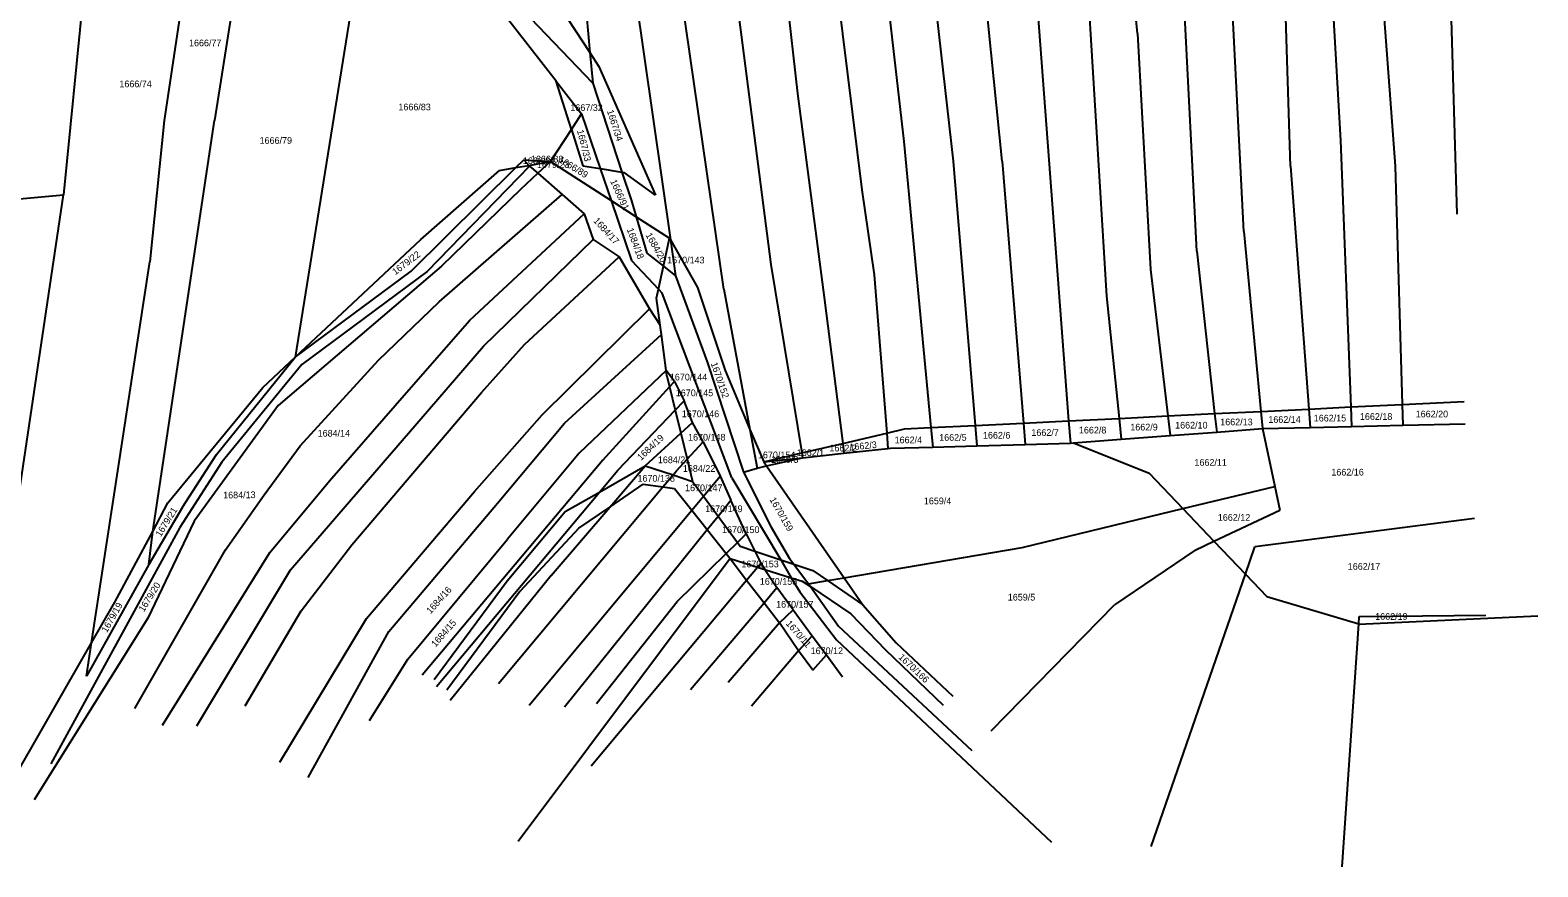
# Model space of a CAD drawing. Extents: x -563148 to -561712, y -1182311 to -1179502.
# Drawn here: x -562099.2 to -561761.9, y -1182279.2 to -1182092.2 of the extents above; entities that cross this region are included whole.
import ezdxf

# ---------------------------------------------------------------- set-up
doc = ezdxf.new("R2010")
doc.units = 0
for name, color, linetype in [('Vrstva 55', 7, 'Continuous'), ('Vrstva 56', 7, 'Continuous'), ('Vrstva 57', 7, 'Continuous')]:
    doc.layers.add(name, color=color, linetype=linetype)

msp = doc.modelspace()

# ---------------------------------------------------------------- linework, layer by layer
at = {"layer": 'Vrstva 55'}
for p, q in [((-561881.77, -1182121.42), (-561894.13, -1181998.39)), ((-561851.53, -1182092.93), (-561858.17, -1182019.92)), ((-561801.14, -1182025.11), (-561793.84, -1182122.58)), ((-561838.25, -1182141.59), (-561843.97, -1182028.63)), ((-561811.3, -1182027.71), (-561806.09, -1182116.85)), ((-561902.61, -1182034.14), (-561892.76, -1182121.42)), ((-562057.84, -1182035.8), (-562069.21, -1182112.37)), ((-561935.36, -1182036.2), (-561927.57, -1182106.3)), ((-561924.37, -1182037.34), (-561913.14, -1182127.84)), ((-561912.92, -1182038.03), (-561903.75, -1182117.07)), ((-562047.11, -1182043.71), (-562057.98, -1182112.37)), ((-562083.82, -1182048.76), (-562091.77, -1182128.98)), ((-562023.2, -1182061.34), (-562039.93, -1182165.3)), ((-561827.71, -1182137.18), (-561831.62, -1182061.07)), ((-561976.59, -1182067.81), (-561973.98, -1182097.18)), ((-561964.91, -1182076.75), (-561955.99, -1182139.02)), ((-561983.82, -1182082.17), (-561973.98, -1182097.18)), ((-561944.07, -1182150.06), (-561954.14, -1182080.19)), ((-561941.77, -1182080.64), (-561933.53, -1182144.56)), ((-561874.18, -1182082.99), (-561866.9, -1182179.5)), ((-561817.29, -1182122.58), (-561818.55, -1182080.87)), ((-561781.6, -1182079.84), (-561780.03, -1182133.27)), ((-561862.53, -1182084.31), (-561858.4, -1182151.67)), ((-561981.56, -1182103.54), (-561993.68, -1182088.01)), ((-561973.38, -1182104.01), (-561988.96, -1182087.75)), ((-561851.53, -1182092.93), (-561848.56, -1182145.71)), ((-561973.98, -1182097.18), (-561973.38, -1182104.01)), ((-561973.98, -1182097.18), (-561971.97, -1182100.26)), ((-561971.97, -1182100.26), (-561959.32, -1182129.02)), ((-561978.15, -1182114.35), (-561981.56, -1182103.54)), ((-561981.56, -1182103.54), (-561975.9, -1182110.89)), ((-561973.38, -1182104.01), (-561966.82, -1182123.89)), ((-561927.57, -1182106.3), (-561921.62, -1182151.9)), ((-562069.21, -1182112.37), (-562072.41, -1182143.99)), ((-562071.8, -1182204.21), (-562057.98, -1182112.37)), ((-561978.15, -1182114.35), (-561975.9, -1182110.89)), ((-561975.9, -1182110.89), (-561971.72, -1182123.11)), ((-561982.85, -1182121.56), (-561978.15, -1182114.35)), ((-561978.15, -1182114.35), (-561975.59, -1182122.49)), ((-561903.75, -1182117.07), (-561897.71, -1182181.01)), ((-561806.09, -1182116.85), (-561803.81, -1182176.41)), ((-562014.01, -1182146.05), (-561990.55, -1182122.9)), ((-561987.5, -1182122.54), (-562010.44, -1182146.1)), ((-561994.24, -1182123.55), (-561990.55, -1182122.9)), ((-561990.55, -1182122.9), (-561988.77, -1182121.15)), ((-561990.55, -1182122.9), (-561987.63, -1182122.4)), ((-561988.77, -1182121.15), (-561987.63, -1182122.4)), ((-561988.77, -1182121.15), (-561982.85, -1182121.56)), ((-561987.63, -1182122.4), (-561982.85, -1182121.56)), ((-561987.63, -1182122.4), (-561987.5, -1182122.54)), ((-561987.5, -1182122.54), (-561985.64, -1182124.17)), ((-561985.64, -1182124.17), (-561982.85, -1182121.56)), ((-561982.85, -1182121.56), (-561969.26, -1182130.27)), ((-561975.59, -1182122.49), (-561971.72, -1182123.11)), ((-561971.72, -1182123.11), (-561969.26, -1182130.27)), ((-561971.72, -1182123.11), (-561966.82, -1182123.89)), ((-561892.76, -1182121.42), (-561887.82, -1182180.52)), ((-561881.77, -1182121.42), (-561876.99, -1182179.99)), ((-561817.29, -1182122.58), (-561813.15, -1182176.86)), ((-561793.84, -1182122.58), (-561792.32, -1182175.84)), ((-562011.84, -1182139), (-561994.24, -1182123.55)), ((-561989.44, -1182127.73), (-561985.64, -1182124.17)), ((-561985.64, -1182124.17), (-561980.21, -1182128.92)), ((-561966.82, -1182123.89), (-561966.3, -1182123.97)), ((-561966.82, -1182123.89), (-561964.68, -1182130.36)), ((-561959.32, -1182129.02), (-561966.3, -1182123.97)), ((-562113.98, -1182278.04), (-562091.77, -1182128.98)), ((-562102.41, -1182129.95), (-562091.77, -1182128.98)), ((-562007.69, -1182152.89), (-561980.21, -1182128.92)), ((-561989.44, -1182127.73), (-562007.2, -1182144.91)), ((-561980.21, -1182128.92), (-561975.3, -1182133.22)), ((-561913.14, -1182127.84), (-561910.4, -1182146.85)), ((-562000.83, -1182156.97), (-561975.3, -1182133.22)), ((-561975.3, -1182133.22), (-561973.24, -1182138.95)), ((-561969.26, -1182130.27), (-561964.68, -1182143.65)), ((-561969.26, -1182130.27), (-561963.65, -1182133.87)), ((-561964.68, -1182130.36), (-561963.65, -1182133.87)), ((-561963.65, -1182133.87), (-561961.24, -1182142.04)), ((-561963.65, -1182133.87), (-561956.2, -1182138.64)), ((-562039.93, -1182165.3), (-562011.84, -1182139)), ((-561997.82, -1182162.81), (-561973.24, -1182138.95)), ((-561973.24, -1182138.95), (-561967.43, -1182142.83)), ((-561957.54, -1182144.94), (-561956.2, -1182138.64)), ((-561956.2, -1182138.64), (-561955.99, -1182139.02)), ((-561955.99, -1182139.02), (-561954.83, -1182147.08)), ((-561955.99, -1182139.02), (-561949.91, -1182149.71)), ((-561827.71, -1182137.18), (-561823.9, -1182177.39)), ((-561988.64, -1182162.47), (-561967.43, -1182142.83)), ((-561967.43, -1182142.83), (-561960.64, -1182154.47)), ((-561964.68, -1182143.65), (-561958.64, -1182150.09)), ((-561961.24, -1182142.04), (-561957.54, -1182144.94)), ((-561838.25, -1182141.59), (-561834.24, -1182177.9)), ((-562085.48, -1182229.17), (-562072.41, -1182143.99)), ((-562007.2, -1182144.91), (-562043.72, -1182176.06)), ((-562039.93, -1182165.3), (-562014.01, -1182146.05)), ((-562010.44, -1182146.1), (-562038.41, -1182166.89)), ((-561958.64, -1182150.09), (-561957.54, -1182144.94)), ((-561957.54, -1182144.94), (-561954.83, -1182147.08)), ((-561933.53, -1182144.56), (-561926.59, -1182186.68)), ((-561910.4, -1182146.85), (-561907.6, -1182182.23)), ((-561848.56, -1182145.71), (-561844.71, -1182178.41)), ((-561959.07, -1182152.09), (-561958.64, -1182150.09)), ((-561958.64, -1182150.09), (-561957.81, -1182150.98)), ((-561954.83, -1182147.08), (-561947.73, -1182166.33)), ((-561949.91, -1182149.71), (-561943.77, -1182168.27)), ((-561944.07, -1182150.06), (-561938.19, -1182181.42)), ((-562021.28, -1182165.97), (-562007.69, -1182152.89)), ((-561958.28, -1182158.1), (-561959.07, -1182152.09)), ((-561942.23, -1182192.24), (-561957.81, -1182150.98)), ((-561921.62, -1182151.9), (-561917.45, -1182184.54)), ((-561858.4, -1182151.67), (-561855.62, -1182178.95)), ((-562015.06, -1182173.19), (-562000.83, -1182156.97)), ((-561984.69, -1182178.17), (-561960.64, -1182154.47)), ((-561960.64, -1182154.47), (-561958.28, -1182158.1)), ((-561979.71, -1182180.06), (-561958, -1182160.23)), ((-561958, -1182160.23), (-561958.28, -1182158.1)), ((-561956.94, -1182168.22), (-561958, -1182160.23)), ((-562009.91, -1182176.8), (-561997.82, -1182162.81)), ((-561998.24, -1182173.19), (-561988.64, -1182162.47)), ((-562057.52, -1182187.06), (-562039.93, -1182165.3)), ((-562038.41, -1182166.89), (-562056.32, -1182188.73)), ((-562047.13, -1182172.04), (-562039.93, -1182165.3)), ((-562038.8, -1182185.06), (-562021.28, -1182165.97)), ((-561947.73, -1182166.33), (-561939.64, -1182190.99)), ((-561956.94, -1182168.22), (-561976.37, -1182186.76)), ((-561955.08, -1182170.68), (-561956.94, -1182168.22)), ((-561956.78, -1182169.45), (-561956.94, -1182168.22)), ((-561956.78, -1182169.45), (-561956.19, -1182171.9)), ((-561956.19, -1182171.9), (-561955.08, -1182170.68)), ((-561955.08, -1182170.68), (-561952.93, -1182175.06)), ((-561943.77, -1182168.27), (-561938.19, -1182181.42)), ((-562068.39, -1182197.84), (-562047.13, -1182172.04)), ((-562032.23, -1182192.94), (-562015.06, -1182173.19)), ((-562027.25, -1182207.19), (-561998.24, -1182173.19)), ((-561971.1, -1182188.27), (-561956.19, -1182171.9)), ((-561956.19, -1182171.9), (-561954.92, -1182177.14)), ((-562043.72, -1182176.06), (-562062.54, -1182201.9)), ((-562040.98, -1182212.85), (-562009.91, -1182176.8)), ((-561967.76, -1182190.56), (-561954.92, -1182177.14)), ((-561954.92, -1182177.14), (-561952.93, -1182175.06)), ((-561954.92, -1182177.14), (-561953.67, -1182182.29)), ((-561951.05, -1182179.89), (-561952.93, -1182175.06)), ((-561834.24, -1182177.9), (-561823.9, -1182177.39)), ((-561823.9, -1182177.39), (-561813.15, -1182176.86)), ((-561823.9, -1182177.39), (-561823.54, -1182181.23)), ((-561813.15, -1182176.86), (-561803.81, -1182176.41)), ((-561813.15, -1182176.86), (-561812.84, -1182180.98)), ((-561803.81, -1182176.41), (-561792.32, -1182175.84)), ((-561803.81, -1182176.41), (-561803.65, -1182180.77)), ((-561792.32, -1182175.84), (-561778.4, -1182175.16)), ((-561792.32, -1182175.84), (-561792.18, -1182180.5)), ((-561999.79, -1182195.34), (-561984.69, -1182178.17)), ((-561994.64, -1182197.92), (-561979.71, -1182180.06)), ((-561953.67, -1182182.29), (-561951.05, -1182179.89)), ((-561948.65, -1182184.18), (-561951.05, -1182179.89)), ((-561897.71, -1182181.01), (-561887.82, -1182180.52)), ((-561887.82, -1182180.52), (-561876.99, -1182179.99)), ((-561887.82, -1182180.52), (-561887.44, -1182185.09)), ((-561876.99, -1182179.99), (-561866.9, -1182179.5)), ((-561876.99, -1182179.99), (-561876.6, -1182184.77)), ((-561866.9, -1182179.5), (-561855.62, -1182178.95)), ((-561866.9, -1182179.5), (-561866.51, -1182184.48)), ((-561855.62, -1182178.95), (-561844.71, -1182178.41)), ((-561855.62, -1182178.95), (-561855.14, -1182183.64)), ((-561844.71, -1182178.41), (-561834.24, -1182177.9)), ((-561844.71, -1182178.41), (-561844.19, -1182182.81)), ((-561834.24, -1182177.9), (-561833.78, -1182182.01)), ((-561812.84, -1182180.98), (-561803.65, -1182180.77)), ((-561803.65, -1182180.77), (-561792.18, -1182180.5)), ((-561792.18, -1182180.5), (-561778.21, -1182180.18)), ((-561961.61, -1182189.57), (-561953.67, -1182182.29)), ((-561953.67, -1182182.29), (-561952.26, -1182188.11)), ((-561938.19, -1182181.42), (-561936.57, -1182190.05)), ((-561938.19, -1182181.42), (-561935.11, -1182188.67)), ((-561917.45, -1182184.54), (-561907.6, -1182182.23)), ((-561907.6, -1182182.23), (-561903.62, -1182181.3)), ((-561907.6, -1182182.23), (-561907.32, -1182185.71)), ((-561903.62, -1182181.3), (-561897.71, -1182181.01)), ((-561897.71, -1182181.01), (-561897.3, -1182185.37)), ((-561865.82, -1182184.46), (-561855.14, -1182183.64)), ((-561855.14, -1182183.64), (-561844.19, -1182182.81)), ((-561844.19, -1182182.81), (-561833.78, -1182182.01)), ((-561833.78, -1182182.01), (-561823.54, -1182181.23)), ((-561823.54, -1182181.23), (-561812.84, -1182180.98)), ((-561823.54, -1182181.23), (-561820.76, -1182194.18)), ((-562065.14, -1182198.78), (-562057.52, -1182187.06)), ((-562046.9, -1182196.04), (-562038.8, -1182185.06)), ((-561976.37, -1182186.76), (-561992.41, -1182205.99)), ((-561952.26, -1182188.11), (-561948.65, -1182184.18)), ((-561948.65, -1182184.18), (-561944.87, -1182191.91)), ((-561935.11, -1182188.67), (-561926.59, -1182186.68)), ((-561926.59, -1182186.68), (-561917.45, -1182184.54)), ((-561926.59, -1182186.68), (-561926.41, -1182187.74)), ((-561926.41, -1182187.74), (-561917.17, -1182186.76)), ((-561917.45, -1182184.54), (-561917.17, -1182186.76)), ((-561917.17, -1182186.76), (-561907.32, -1182185.71)), ((-561907.32, -1182185.71), (-561906.79, -1182185.65)), ((-561906.79, -1182185.65), (-561897.3, -1182185.37)), ((-561897.3, -1182185.37), (-561887.44, -1182185.09)), ((-561887.44, -1182185.09), (-561876.6, -1182184.77)), ((-561876.6, -1182184.77), (-561866.51, -1182184.48)), ((-561866.51, -1182184.48), (-561865.82, -1182184.46)), ((-561865.82, -1182184.46), (-561848.91, -1182191.2)), ((-562056.32, -1182188.73), (-562065.73, -1182203.37)), ((-561971.1, -1182188.27), (-562011.55, -1182236.39)), ((-561971.84, -1182195.42), (-561961.61, -1182189.57)), ((-561971.84, -1182195.42), (-561967.76, -1182190.56)), ((-561969.51, -1182198.78), (-561961.61, -1182189.57)), ((-561961.61, -1182189.57), (-561955.4, -1182191.61)), ((-561955.4, -1182191.61), (-561954.65, -1182190.71)), ((-561954.65, -1182190.71), (-561952.26, -1182188.11)), ((-561952.26, -1182188.11), (-561951.06, -1182193.04)), ((-561939.64, -1182190.99), (-561936.57, -1182190.05)), ((-561936.57, -1182190.05), (-561934.48, -1182189.58)), ((-561935.11, -1182188.67), (-561926.41, -1182187.74)), ((-561935.11, -1182188.67), (-561934.48, -1182189.58)), ((-561934.48, -1182189.58), (-561926.41, -1182187.74)), ((-561934.48, -1182189.58), (-561917.15, -1182214.59)), ((-562045.61, -1182208.91), (-562032.23, -1182192.94)), ((-561994.47, -1182238.26), (-561957.65, -1182194.29)), ((-561969.51, -1182198.78), (-561962.05, -1182193.68)), ((-561962.05, -1182193.68), (-561957.65, -1182194.29)), ((-561957.65, -1182194.29), (-561955.4, -1182191.61)), ((-561957.65, -1182194.29), (-561955.11, -1182194.64)), ((-561955.4, -1182191.61), (-561951.06, -1182193.04)), ((-561948.6, -1182196.37), (-561944.87, -1182191.91)), ((-561944.87, -1182191.91), (-561942.47, -1182197.23)), ((-561942.23, -1182192.24), (-561931.32, -1182210.56)), ((-561939.64, -1182190.99), (-561933.43, -1182203.31)), ((-561848.91, -1182191.2), (-561841.33, -1182199.14)), ((-561841.33, -1182199.14), (-561820.76, -1182194.18)), ((-561820.76, -1182194.18), (-561819.63, -1182199.47)), ((-562055.53, -1182208.34), (-562046.9, -1182196.04)), ((-562023.99, -1182223.67), (-561999.79, -1182195.34)), ((-562008.35, -1182238.87), (-561971.84, -1182195.42)), ((-561979.53, -1182199.81), (-561971.84, -1182195.42)), ((-561955.11, -1182194.64), (-561951.22, -1182199.51)), ((-561951.22, -1182199.51), (-561948.6, -1182196.37)), ((-561945.34, -1182200.79), (-561942.47, -1182197.23)), ((-561939.04, -1182204.78), (-561942.47, -1182197.23)), ((-562065.14, -1182198.78), (-562072.69, -1182211.61)), ((-562071.8, -1182204.21), (-562068.39, -1182197.84)), ((-562019.01, -1182226.59), (-561994.64, -1182197.92)), ((-561992.52, -1182215.24), (-561979.53, -1182199.81)), ((-561987.61, -1182243.07), (-561951.22, -1182199.51)), ((-561982.63, -1182214.06), (-561969.51, -1182198.78)), ((-561976.44, -1182203.51), (-561969.51, -1182198.78)), ((-561951.22, -1182199.51), (-561947.78, -1182203.82)), ((-561947.78, -1182203.82), (-561945.34, -1182200.79)), ((-561877.28, -1182207.81), (-561841.33, -1182199.14)), ((-561841.33, -1182199.14), (-561834.4, -1182206.4)), ((-561834.4, -1182206.4), (-561819.63, -1182199.47)), ((-562065.73, -1182203.37), (-562094.62, -1182256.2)), ((-562080.25, -1182220.03), (-562071.8, -1182204.21)), ((-562062.54, -1182201.9), (-562072.91, -1182223.65)), ((-562072.69, -1182211.61), (-562071.8, -1182204.21)), ((-561976.44, -1182203.51), (-561989.67, -1182217.65)), ((-561979.71, -1182243.42), (-561947.78, -1182203.82)), ((-561947.78, -1182203.82), (-561943.51, -1182209.16)), ((-561933.43, -1182203.31), (-561929.32, -1182210.3)), ((-561776.11, -1182201.34), (-561825.23, -1182207.65)), ((-562038.58, -1182221.95), (-562027.25, -1182207.19)), ((-562014.72, -1182232.77), (-561992.41, -1182205.99)), ((-561943.51, -1182209.16), (-561940.98, -1182206.68)), ((-561940.98, -1182206.68), (-561939.04, -1182204.78)), ((-561939.04, -1182204.78), (-561937.12, -1182208.61)), ((-561838.63, -1182208.39), (-561834.4, -1182206.4)), ((-561834.4, -1182206.4), (-561827.36, -1182213.78)), ((-561827.36, -1182213.78), (-561825.23, -1182207.65)), ((-562075.8, -1182243.8), (-562055.53, -1182208.34)), ((-562069.64, -1182247.54), (-562045.61, -1182208.91)), ((-561942.63, -1182210.26), (-561990.02, -1182273.57)), ((-561954.48, -1182219.89), (-561943.51, -1182209.16)), ((-561943.51, -1182209.16), (-561942.63, -1182210.26)), ((-561942.63, -1182210.26), (-561938.94, -1182215.1)), ((-561937.12, -1182208.61), (-561935.77, -1182211.31)), ((-561931.32, -1182210.56), (-561928.94, -1182214.57)), ((-561929.32, -1182210.3), (-561928.4, -1182211.54)), ((-561917.15, -1182214.59), (-561877.28, -1182207.81)), ((-561838.63, -1182208.39), (-561856.62, -1182220.64)), ((-562072.69, -1182211.61), (-562086.61, -1182236.55)), ((-562061.92, -1182247.71), (-562040.98, -1182212.85)), ((-561982.63, -1182214.06), (-562005.28, -1182242.04)), ((-561938.94, -1182215.1), (-561936.5, -1182212.19)), ((-561936.5, -1182212.19), (-561935.77, -1182211.31)), ((-561935.77, -1182211.31), (-561934.86, -1182212.71)), ((-561934.86, -1182212.71), (-561932.17, -1182216.8)), ((-561928.4, -1182211.54), (-561925.11, -1182215.94)), ((-561848.44, -1182274.63), (-561827.36, -1182213.78)), ((-561827.36, -1182213.78), (-561822.57, -1182218.8)), ((-562008.87, -1182237.31), (-561992.52, -1182215.24)), ((-561989.67, -1182217.65), (-562005.97, -1182239.71)), ((-561973.7, -1182256.64), (-561938.94, -1182215.1)), ((-561938.94, -1182215.1), (-561935.05, -1182220.19)), ((-561935.05, -1182220.19), (-561932.17, -1182216.8)), ((-561928.53, -1182221.74), (-561932.17, -1182216.8)), ((-561928.94, -1182214.57), (-561927.03, -1182217.77)), ((-561927.03, -1182217.77), (-561918.8, -1182228.49)), ((-561925.11, -1182215.94), (-561920.86, -1182215.22)), ((-561925.11, -1182215.94), (-561924.68, -1182216.54)), ((-561924.68, -1182216.54), (-561918.41, -1182225.42)), ((-561920.86, -1182215.22), (-561917.15, -1182214.59)), ((-561917.15, -1182214.59), (-561912.94, -1182220.67)), ((-562085.48, -1182229.17), (-562080.25, -1182220.03)), ((-561972.5, -1182242.73), (-561954.48, -1182219.89)), ((-561951.52, -1182239.56), (-561935.05, -1182220.19)), ((-561935.05, -1182220.19), (-561931.61, -1182224.7)), ((-561912.94, -1182220.67), (-561905.46, -1182229.13)), ((-561884.26, -1182248.78), (-561856.62, -1182220.64)), ((-561822.57, -1182218.8), (-561802.02, -1182224.92)), ((-562072.91, -1182223.65), (-562098.29, -1182264.27)), ((-562051.11, -1182243.24), (-562038.58, -1182221.95)), ((-562043.38, -1182255.78), (-562023.99, -1182223.67)), ((-561931.61, -1182224.7), (-561928.53, -1182221.74)), ((-561928.53, -1182221.74), (-561924.24, -1182227.55)), ((-561802.02, -1182224.92), (-561801.91, -1182223.26)), ((-561802, -1182224.93), (-561761.94, -1182223.1)), ((-561801.91, -1182223.26), (-561773.6, -1182222.95)), ((-562037.03, -1182259.21), (-562019.01, -1182226.59)), ((-561931.61, -1182224.7), (-561943.05, -1182238.02)), ((-561927.3, -1182230.95), (-561931.61, -1182224.7)), ((-561927.3, -1182230.95), (-561924.24, -1182227.55)), ((-561924.24, -1182227.55), (-561921.08, -1182231.83)), ((-561918.41, -1182225.42), (-561888.57, -1182253.17)), ((-561805.7, -1182279.21), (-561802.02, -1182224.92)), ((-561802.02, -1182224.92), (-561802, -1182224.93)), ((-562104.1, -1182261.73), (-562085.48, -1182229.17)), ((-562086.61, -1182236.55), (-562085.48, -1182229.17)), ((-561927.3, -1182230.95), (-561937.86, -1182243.3)), ((-561924.14, -1182235.26), (-561927.3, -1182230.95)), ((-561918.8, -1182228.49), (-561870.77, -1182273.66)), ((-561905.46, -1182229.13), (-561892.79, -1182241.08)), ((-562023.3, -1182246.51), (-562014.72, -1182232.77)), ((-561924.14, -1182235.26), (-561921.08, -1182231.83)), ((-561921.08, -1182231.83), (-561917.47, -1182236.72))]:
    msp.add_line(p, q, dxfattribs=at)
at = {"layer": 'Vrstva 56'}
for p, q in [((-561951.06, -1182193.04), (-561948.6, -1182196.37)), ((-561948.6, -1182196.37), (-561945.34, -1182200.79)), ((-561945.34, -1182200.79), (-561940.98, -1182206.68)), ((-561940.98, -1182206.68), (-561940.35, -1182207.53)), ((-561940.35, -1182207.53), (-561937.12, -1182208.61)), ((-561942.63, -1182210.26), (-561936.5, -1182212.19)), ((-561937.12, -1182208.61), (-561931.32, -1182210.56)), ((-561931.32, -1182210.56), (-561928.4, -1182211.54)), ((-561936.5, -1182212.19), (-561934.86, -1182212.71)), ((-561934.86, -1182212.71), (-561928.94, -1182214.57)), ((-561928.4, -1182211.54), (-561924.13, -1182212.97)), ((-561924.13, -1182212.97), (-561920.86, -1182215.22)), ((-561928.94, -1182214.57), (-561926.48, -1182215.34)), ((-561926.48, -1182215.34), (-561924.68, -1182216.54)), ((-561924.68, -1182216.54), (-561915.6, -1182222.63)), ((-561920.86, -1182215.22), (-561912.94, -1182220.67)), ((-561915.6, -1182222.63), (-561907.86, -1182230.71)), ((-561907.86, -1182230.71), (-561894.97, -1182243.1))]:
    msp.add_line(p, q, dxfattribs=at)

# ---------------------------------------------------------------- texts
at = {"layer": 'Vrstva 57'}
for s, p in [('1666/77', (-562063.68, -1182095.77)), ('1666/74', (-562079.26, -1182104.93)), ('1666/83', (-562016.84, -1182110.09)), ('1667/32', (-561978.37, -1182110.24)), ('1666/79', (-562047.89, -1182117.58)), ('1666/87', (-561989.01, -1182122.11)), ('1666/88', (-561987.19, -1182121.74)), ('1679/23', (-561985.85, -1182122.96)), ('1670/143', (-561956.72, -1182144.31)), ('1670/144', (-561956.11, -1182170.48)), ('1670/145', (-561954.78, -1182174)), ('1670/146', (-561953.44, -1182178.69)), ('1662/20', (-561789.27, -1182178.74)), ('1662/8', (-561864.6, -1182182.33)), ('1662/9', (-561853.11, -1182181.66)), ('1662/10', (-561843.08, -1182181.23)), ('1662/13', (-561832.99, -1182180.5)), ('1662/14', (-561822.23, -1182179.96)), ('1662/15', (-561812.07, -1182179.65)), ('1662/18', (-561801.74, -1182179.29)), ('1684/14', (-562034.9, -1182183.03)), ('1670/148', (-561952.04, -1182183.92)), ('1662/4', (-561905.83, -1182184.52)), ('1662/5', (-561895.86, -1182183.97)), ('1662/6', (-561886.07, -1182183.48)), ('1662/7', (-561875.24, -1182182.87)), ('1684/21', (-561958.79, -1182188.97)), ('1670/154', (-561936.41, -1182187.87)), ('1659/3', (-561933.49, -1182188.9)), ('1662/1', (-561927.72, -1182187.38)), ('1662/2', (-561920.42, -1182186.35)), ('1684/22', (-561953.2, -1182190.91)), ('1662/11', (-561838.76, -1182189.56)), ('1662/16', (-561808.13, -1182191.73)), ('1670/138', (-561963.35, -1182193.1)), ('1670/147', (-561952.71, -1182195.23)), ('1659/4', (-561899.29, -1182198.15)), ('1670/149', (-561948.21, -1182199.92)), ('1662/12', (-561833.53, -1182201.85)), ('1670/150', (-561944.44, -1182204.6)), ('1670/153', (-561940.12, -1182212.26)), ('1662/17', (-561804.46, -1182212.81)), ('1670/155', (-561935.99, -1182216.16)), ('1670/157', (-561932.34, -1182221.27)), ('1659/5', (-561880.51, -1182219.68)), ('1662/19', (-561798.33, -1182224)), ('1670/12', (-561924.62, -1182231.66))]:
    msp.add_text(s, height=1.5, dxfattribs=at).set_placement(p)
for s, rotation, p in [('1667/34', 288.1179, (-561970.22, -1182110.24)), ('1667/33', 284.1053, (-561976.91, -1182114.62)), ('1666/89', 328.1615, (-561981.17, -1182121.5)), ('1666/91', 294.3256, (-561969.49, -1182125.94)), ('1684/17', 312.5485, (-561973.32, -1182134.88)), ('1684/18', 290.5274, (-561965.78, -1182136.7)), ('1684/20', 299.3008, (-561961.59, -1182137.98)), ('1679/22', 37.1959, (-562017.53, -1182146.98)), ('1670/152', 289.2601, (-561946.99, -1182166.7)), ('1684/19', 43.491, (-561962.56, -1182188.47)), ('1662/3', 5.7487, (-561915.86, -1182186.16)), ('1684/13', 0.7252, (-562056.03, -1182196.87)), ('1670/159', 299.8194, (-561933.86, -1182197.11)), ('1679/21', 58.1995, (-562070.01, -1182205.57)), ('1679/20', 58.1666, (-562073.78, -1182222.35)), ('1684/16', 48.2238, (-562009.62, -1182222.78)), ('1679/19', 60.2551, (-562082.05, -1182226.98)), ('1684/15', 48.996, (-562008.52, -1182230.2)), ('1670/11', 311.2925, (-561930.27, -1182224.91)), ('1670/166', 316.851, (-561905.1, -1182232.51))]:
    msp.add_text(s, height=1.5, rotation=rotation, dxfattribs=at).set_placement(p)

doc.saveas('drawing.dxf')
